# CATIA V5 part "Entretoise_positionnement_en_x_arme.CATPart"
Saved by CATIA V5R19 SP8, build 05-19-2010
Part number: Entretoise_positionnement_en_x_arme
Bounding box of the stored display mesh (mm): x -59.167 to -24.431, y -157.809 to -142.809, z 1304.765 to 1319.683
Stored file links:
  G:\EU_thinkMotion\CFAO_2010\MMS_groupe2\MMS_groupe2\OK\nrosalie\nrosalie_cfao_support_d_arme_legere_final\Entretoise_positionnement_en_x_arme.CATPart
  G:\EU_thinkMotion\CFAO_2010\MMS_groupe2\MMS_groupe2\OK\nrosalie\nrosalie_cfao_support_d_arme_legere_final\nrosalie_Support_d_arme_legere.CATProduct
  G:\EU_thinkMotion\CFAO_2010\MMS_groupe2\MMS_groupe2\OK\nrosalie\nrosalie_cfao_support_d_arme_legere_final\Squelette_Systeme_de_visee.CATPart
  G:\EU_thinkMotion\CFAO_2010\MMS_groupe2\MMS_groupe2\OK\nrosalie\nrosalie_cfao_support_d_arme_legere_final\Arme.CATPart
  G:\EU_thinkMotion\CFAO_2010\MMS_groupe2\MMS_groupe2\OK\nrosalie\nrosalie_cfao_support_d_arme_legere_final\Bras.CATPart
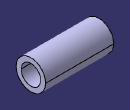
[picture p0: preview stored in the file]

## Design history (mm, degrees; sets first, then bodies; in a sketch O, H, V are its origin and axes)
Set1
  Sketch1 on Plane1, origin (-50, 0, 0), H (0, 1, 0), V (0, 0, 1)
    projected circle E1 centre (-150.3087, 1312.2241) radius 5 from edge of DatumCurve1
    circle A1 centre (-150.3087, 1312.2241) radius 7.5
    concentricity: A1 E1
Set2
  Plane1 "Plan_limite_largeur_arme_en_x-": linked copy from another document
  DatumCurve1: linked copy from another document
  DatumSurface1: linked copy from another document
  DatumSurface2: linked copy from another document
Body1 (main body)
  Pad1: profile Sketch1, direction (1, 0, 0), up to face of DatumSurface1, opposite side up to face of DatumSurface2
